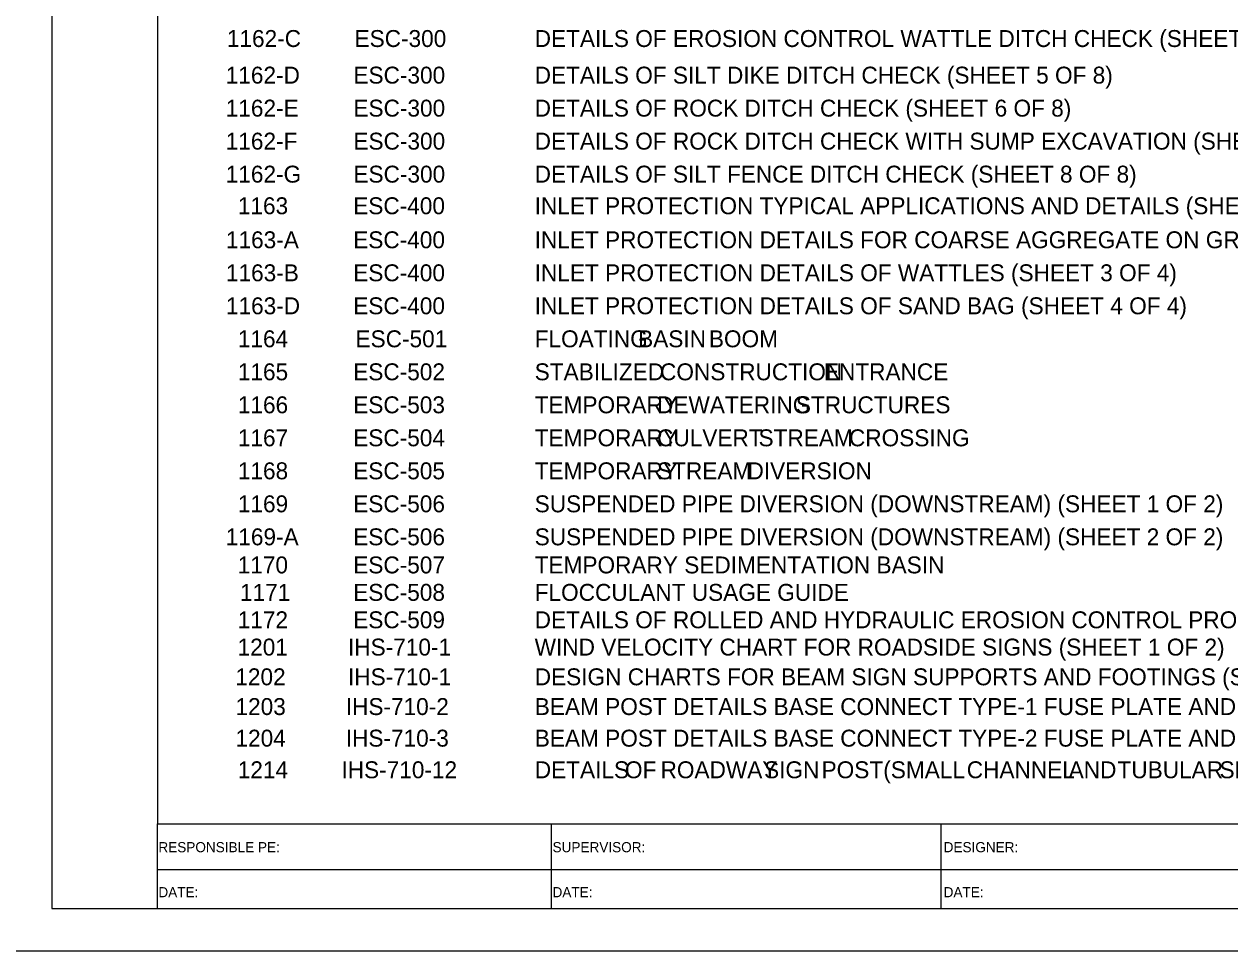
# Model space of a CAD drawing. Extents: x -12822 to 16384, y -6351 to 1913.
# Drawn here: x -804 to -91, y -4850 to -4303 of the extents above; entities that cross this region are included whole.
import ezdxf

# ---------------------------------------------------------------- set-up
doc = ezdxf.new("R2010")
doc.units = 0
for name, color, linetype in [('ANNO-TXT', 7, 'Continuous'), ('Level 10', 7, 'Continuous'), ('Level 62', 7, 'Continuous'), ('SHT-BDR', 7, 'Continuous'), ('SHT-BNDRY', 7, 'Continuous')]:
    doc.layers.add(name, color=color, linetype=linetype)

msp = doc.modelspace()

# ---------------------------------------------------------------- linework, layer by layer
at = {"layer": 'Level 62'}
msp.add_lwpolyline([(-850.02, -4850.34), (849.98, -4850.34), (849.98, -3750.34), (-850.02, -3750.34)], close=True, dxfattribs=at)
at = {"layer": 'SHT-BDR'}
msp.add_lwpolyline([(-725.04, -4775.29), (774.96, -4775.29), (774.96, -3825.29), (-725.04, -3825.29)], close=True, dxfattribs=at)
at = {"layer": 'SHT-BNDRY'}
for p, q in [((-725.04, -4825.34), (-725.04, -4775.29)), ((-492.43, -4775.29), (-492.43, -4825.34)), ((-261.71, -4825.34), (-261.71, -4775.29)), ((-725.04, -4802.29), (53.1, -4802.29))]:
    msp.add_line(p, q, dxfattribs=at)
msp.add_lwpolyline([(-787.52, -4825.34), (824.98, -4825.34), (824.98, -3775.34), (-787.52, -3775.34)], close=True, dxfattribs=at)

# ---------------------------------------------------------------- texts
at = {"layer": 'ANNO-TXT'}
for s, p in [('RESPONSIBLE PE:', (-724.57, -4792.07)), ('SUPERVISOR:', (-491.55, -4792.07)), ('DESIGNER:', (-260.33, -4792.07)), ('DATE:', (-724.57, -4818.67)), ('DATE:', (-491.55, -4818.67)), ('DATE:', (-260.33, -4818.67))]:
    msp.add_text(s, height=6, rotation=360, dxfattribs=at).set_placement(p)
at = {"layer": 'Level 10'}
for s, p in [('1162-C', (-684.1, -4316.3)), ('ESC-300', (-608.62, -4316.3)), ('DETAILS OF EROSION CONTROL WATTLE DITCH CHECK (SHEET 4 OF 8)', (-502.11, -4316.3)), ('1162-D', (-684.77, -4337.93)), ('ESC-300', (-609.28, -4337.93)), ('DETAILS OF SILT DIKE DITCH CHECK (SHEET 5 OF 8)', (-502.11, -4337.93)), ('1162-E', (-684.77, -4357.43)), ('ESC-300', (-609.28, -4357.43)), ('DETAILS OF ROCK DITCH CHECK (SHEET 6 OF 8)', (-502.11, -4357.43)), ('1162-F', (-684.77, -4376.93)), ('ESC-300', (-609.28, -4376.93)), ('DETAILS OF ROCK DITCH CHECK WITH SUMP EXCAVATION (SHEET 7 OF 8)', (-502.11, -4376.93)), ('1162-G', (-684.77, -4396.43)), ('ESC-300', (-609.28, -4396.43)), ('DETAILS OF SILT FENCE DITCH CHECK (SHEET 8 OF 8)', (-502.11, -4396.43)), ('1163', (-677.61, -4415.11)), ('ESC-400', (-609.4, -4415.11)), ('INLET PROTECTION TYPICAL APPLICATIONS AND DETAILS (SHEET 1 OF 4)', (-502.11, -4415.11)), ('1163-A', (-684.65, -4435.22)), ('ESC-400', (-609.4, -4435.22)), ('INLET PROTECTION DETAILS FOR COARSE AGGREGATE ON GRADES AND SAGS (SHEET 2 OF 4)', (-502.11, -4435.22)), ('1163-B', (-684.65, -4454.72)), ('ESC-400', (-609.4, -4454.72)), ('INLET PROTECTION DETAILS OF WATTLES (SHEET 3 OF 4)', (-502.11, -4454.72)), ('1163-D', (-684.65, -4474.22)), ('ESC-400', (-609.4, -4474.22)), ('INLET PROTECTION DETAILS OF SAND BAG (SHEET 4 OF 4)', (-502.11, -4474.22)), ('1164', (-677.61, -4493.72)), ('ESC-501', (-608.04, -4493.72)), ('FLOATING', (-502.11, -4493.72)), (' BASIN', (-444.67, -4493.72)), (' BOOM', (-402.83, -4493.72)), ('1165', (-677.61, -4513.22)), ('ESC-502', (-609.4, -4513.22)), ('STABILIZED', (-502.11, -4513.22)), (' CONSTRUCTION', (-431.71, -4513.22)), (' ENTRANCE', (-334.83, -4513.22)), ('1166', (-677.61, -4532.72)), ('ESC-503', (-609.4, -4532.72)), ('TEMPORARY', (-502.11, -4532.72)), (' DEWATERING', (-433.47, -4532.72)), (' STRUCTURES', (-351.39, -4532.72)), ('1167', (-677.61, -4552.22)), ('ESC-504', (-609.4, -4552.22)), ('TEMPORARY', (-502.11, -4552.22)), (' CULVERT', (-433.47, -4552.22)), (' STREAM', (-373.47, -4552.22)), (' CROSSING', (-320.03, -4552.22)), ('1168', (-677.61, -4571.72)), ('ESC-505', (-609.4, -4571.72)), ('TEMPORARY', (-502.11, -4571.72)), (' STREAM', (-433.47, -4571.72)), (' DIVERSION', (-380.03, -4571.72)), ('1169', (-677.61, -4591.22)), ('ESC-506', (-609.4, -4591.22)), ('SUSPENDED PIPE DIVERSION (DOWNSTREAM) (SHEET 1 OF 2)', (-502.11, -4591.22)), ('1169-A', (-684.77, -4610.72)), ('ESC-506', (-609.4, -4610.72)), ('SUSPENDED PIPE DIVERSION (DOWNSTREAM) (SHEET 2 OF 2)', (-502.11, -4610.72)), ('1170', (-677.69, -4627.32)), ('ESC-507', (-609.4, -4627.32)), ('TEMPORARY SEDIMENTATION BASIN', (-502.11, -4627.32)), ('1171', (-676.33, -4643.53)), ('ESC-508', (-609.4, -4643.53)), ('FLOCCULANT USAGE GUIDE', (-502.11, -4643.53)), ('1172', (-677.69, -4659.74)), ('ESC-509', (-609.4, -4659.74)), ('DETAILS OF ROLLED AND HYDRAULIC EROSION CONTROL PRODUCT INSTALLATION', (-502.11, -4659.74)), ('1201', (-677.76, -4675.86)), ('IHS-710-1', (-612.48, -4675.86)), ('WIND VELOCITY CHART FOR ROADSIDE SIGNS (SHEET 1 OF 2)', (-502.11, -4675.86)), ('1202', (-679.09, -4693.43)), ('IHS-710-1', (-612.46, -4693.43)), ('DESIGN CHARTS FOR BEAM SIGN SUPPORTS AND FOOTINGS (SHEET 2 OF 2)', (-502.08, -4693.43)), ('1203', (-679, -4711)), ('IHS-710-2', (-613.79, -4711)), ('BEAM POST DETAILS BASE CONNECT TYPE-1 FUSE PLATE AND HINGE FOR POST 66" OR GREATER APART', (-502.05, -4711)), ('1204', (-679, -4729.67)), ('IHS-710-3', (-613.79, -4729.67)), ('BEAM POST DETAILS BASE CONNECT TYPE-2 FUSE PLATE AND HINGE FOR POST 66" OR LESS APART', (-502.05, -4729.67)), ('1214', (-677.64, -4748.35)), ('IHS-710-12', (-616.35, -4748.35)), ('DETAILS', (-502.05, -4748.35)), (' OF', (-452.45, -4748.35)), (' ROADWAY', (-431.41, -4748.35)), (' SIGN', (-370.21, -4748.35)), (' POST', (-336.21, -4748.35)), (' (SMALL', (-299.73, -4748.35)), (' CHANNEL', (-250.37, -4748.35)), (' AND', (-190.13, -4748.35)), (' TUBULAR', (-161.25, -4748.35)), (' SECTION)', (-100.93, -4748.35))]:
    msp.add_text(s, height=10, dxfattribs=at).set_placement(p)

doc.saveas('drawing.dxf')
